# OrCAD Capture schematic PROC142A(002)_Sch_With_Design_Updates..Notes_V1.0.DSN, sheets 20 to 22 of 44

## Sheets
20 19. SD CARD INTERFACE: size C; title: SD CARD INTERFACE
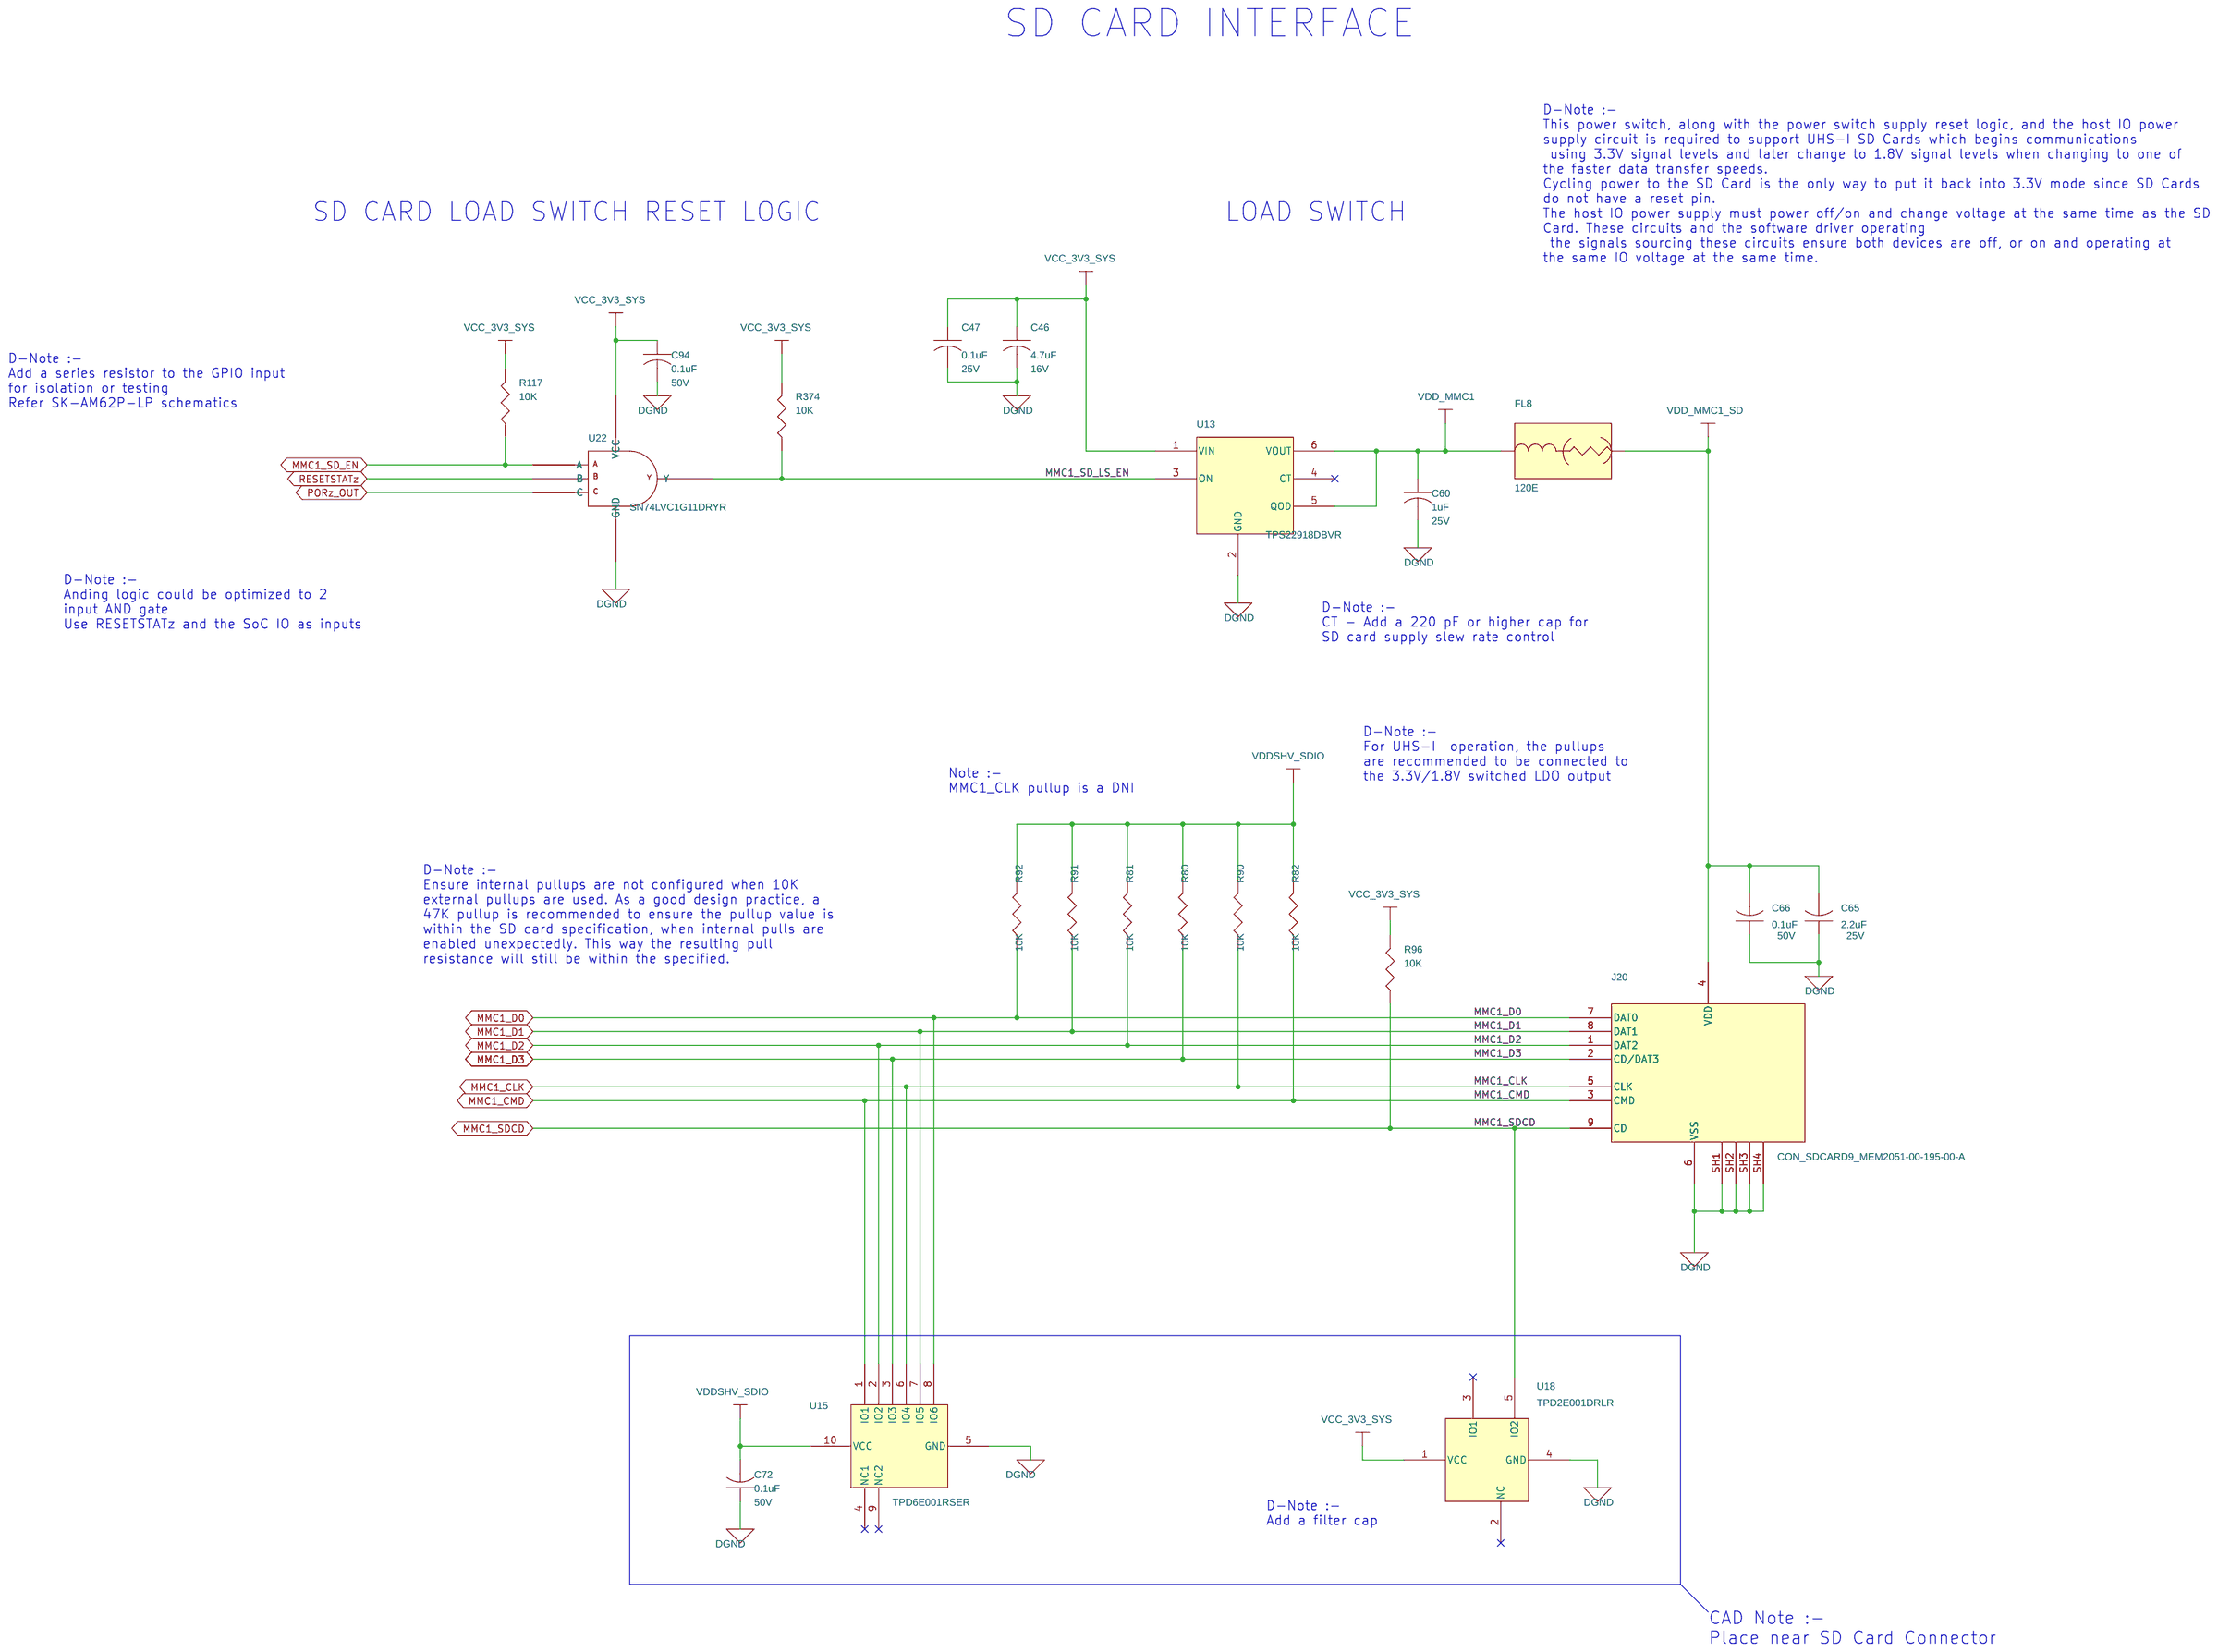
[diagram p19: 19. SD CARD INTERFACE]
21 20. OSPI INTERFACE: size C; title: OSPI INTERFACE
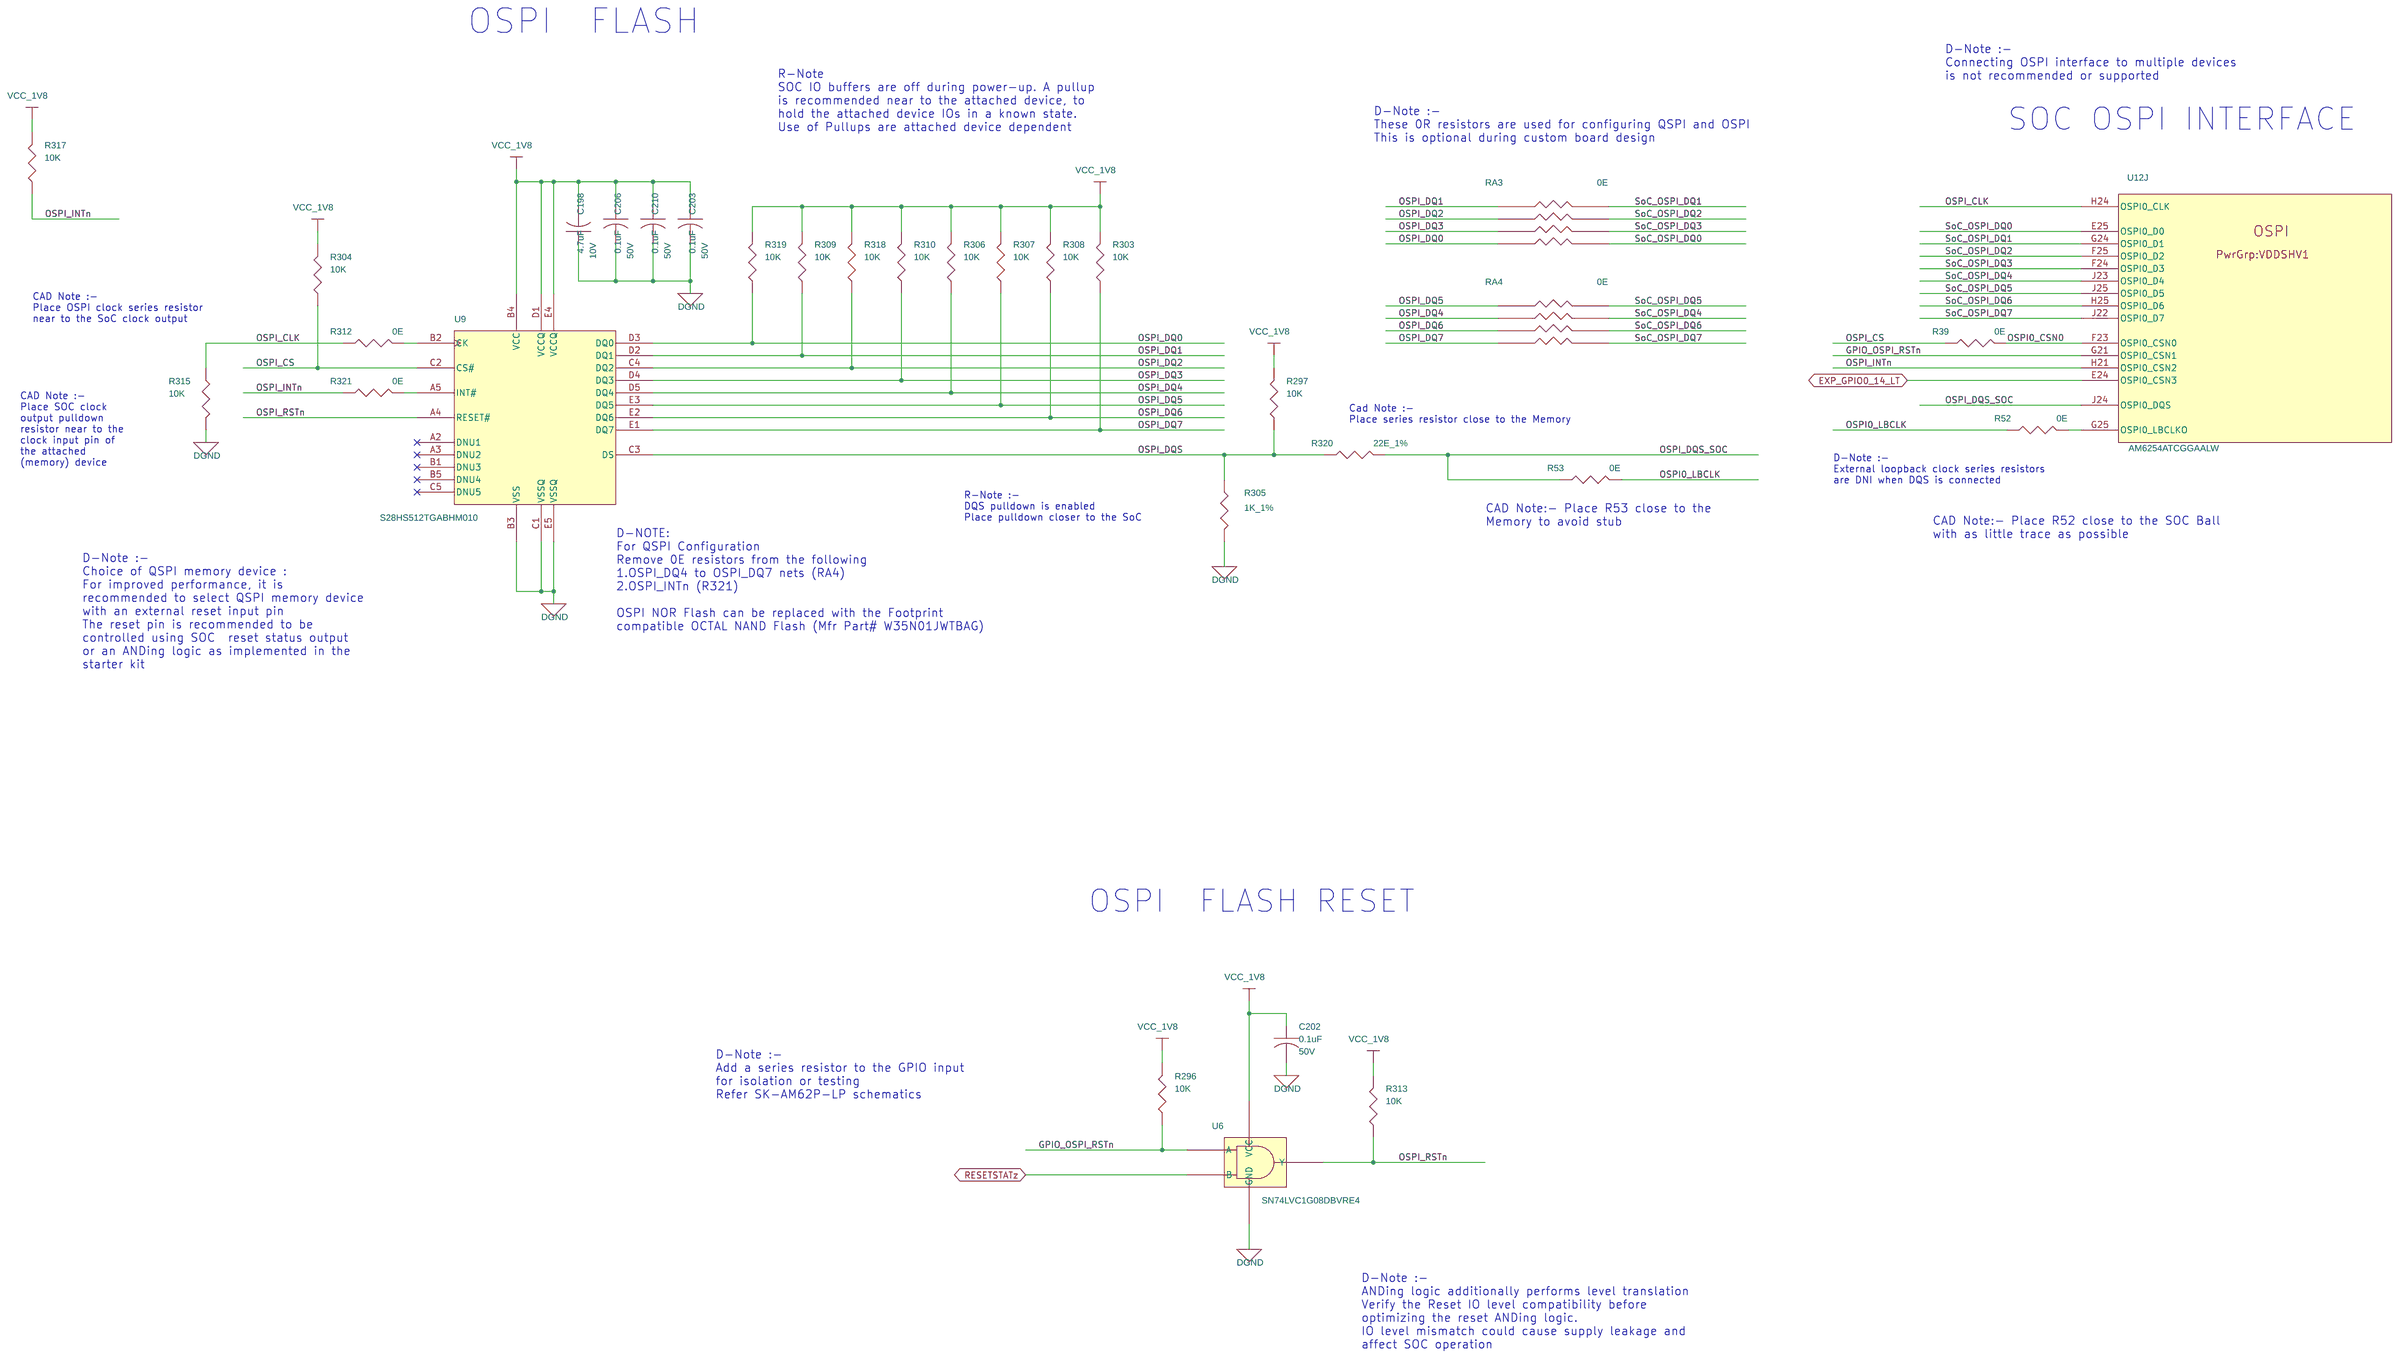
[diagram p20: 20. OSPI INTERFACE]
22 21. BRD ID EEPROM &TEMP SENSORS: size C; title: BOARD ID EEPROM & TEMPERATURE SENSORS
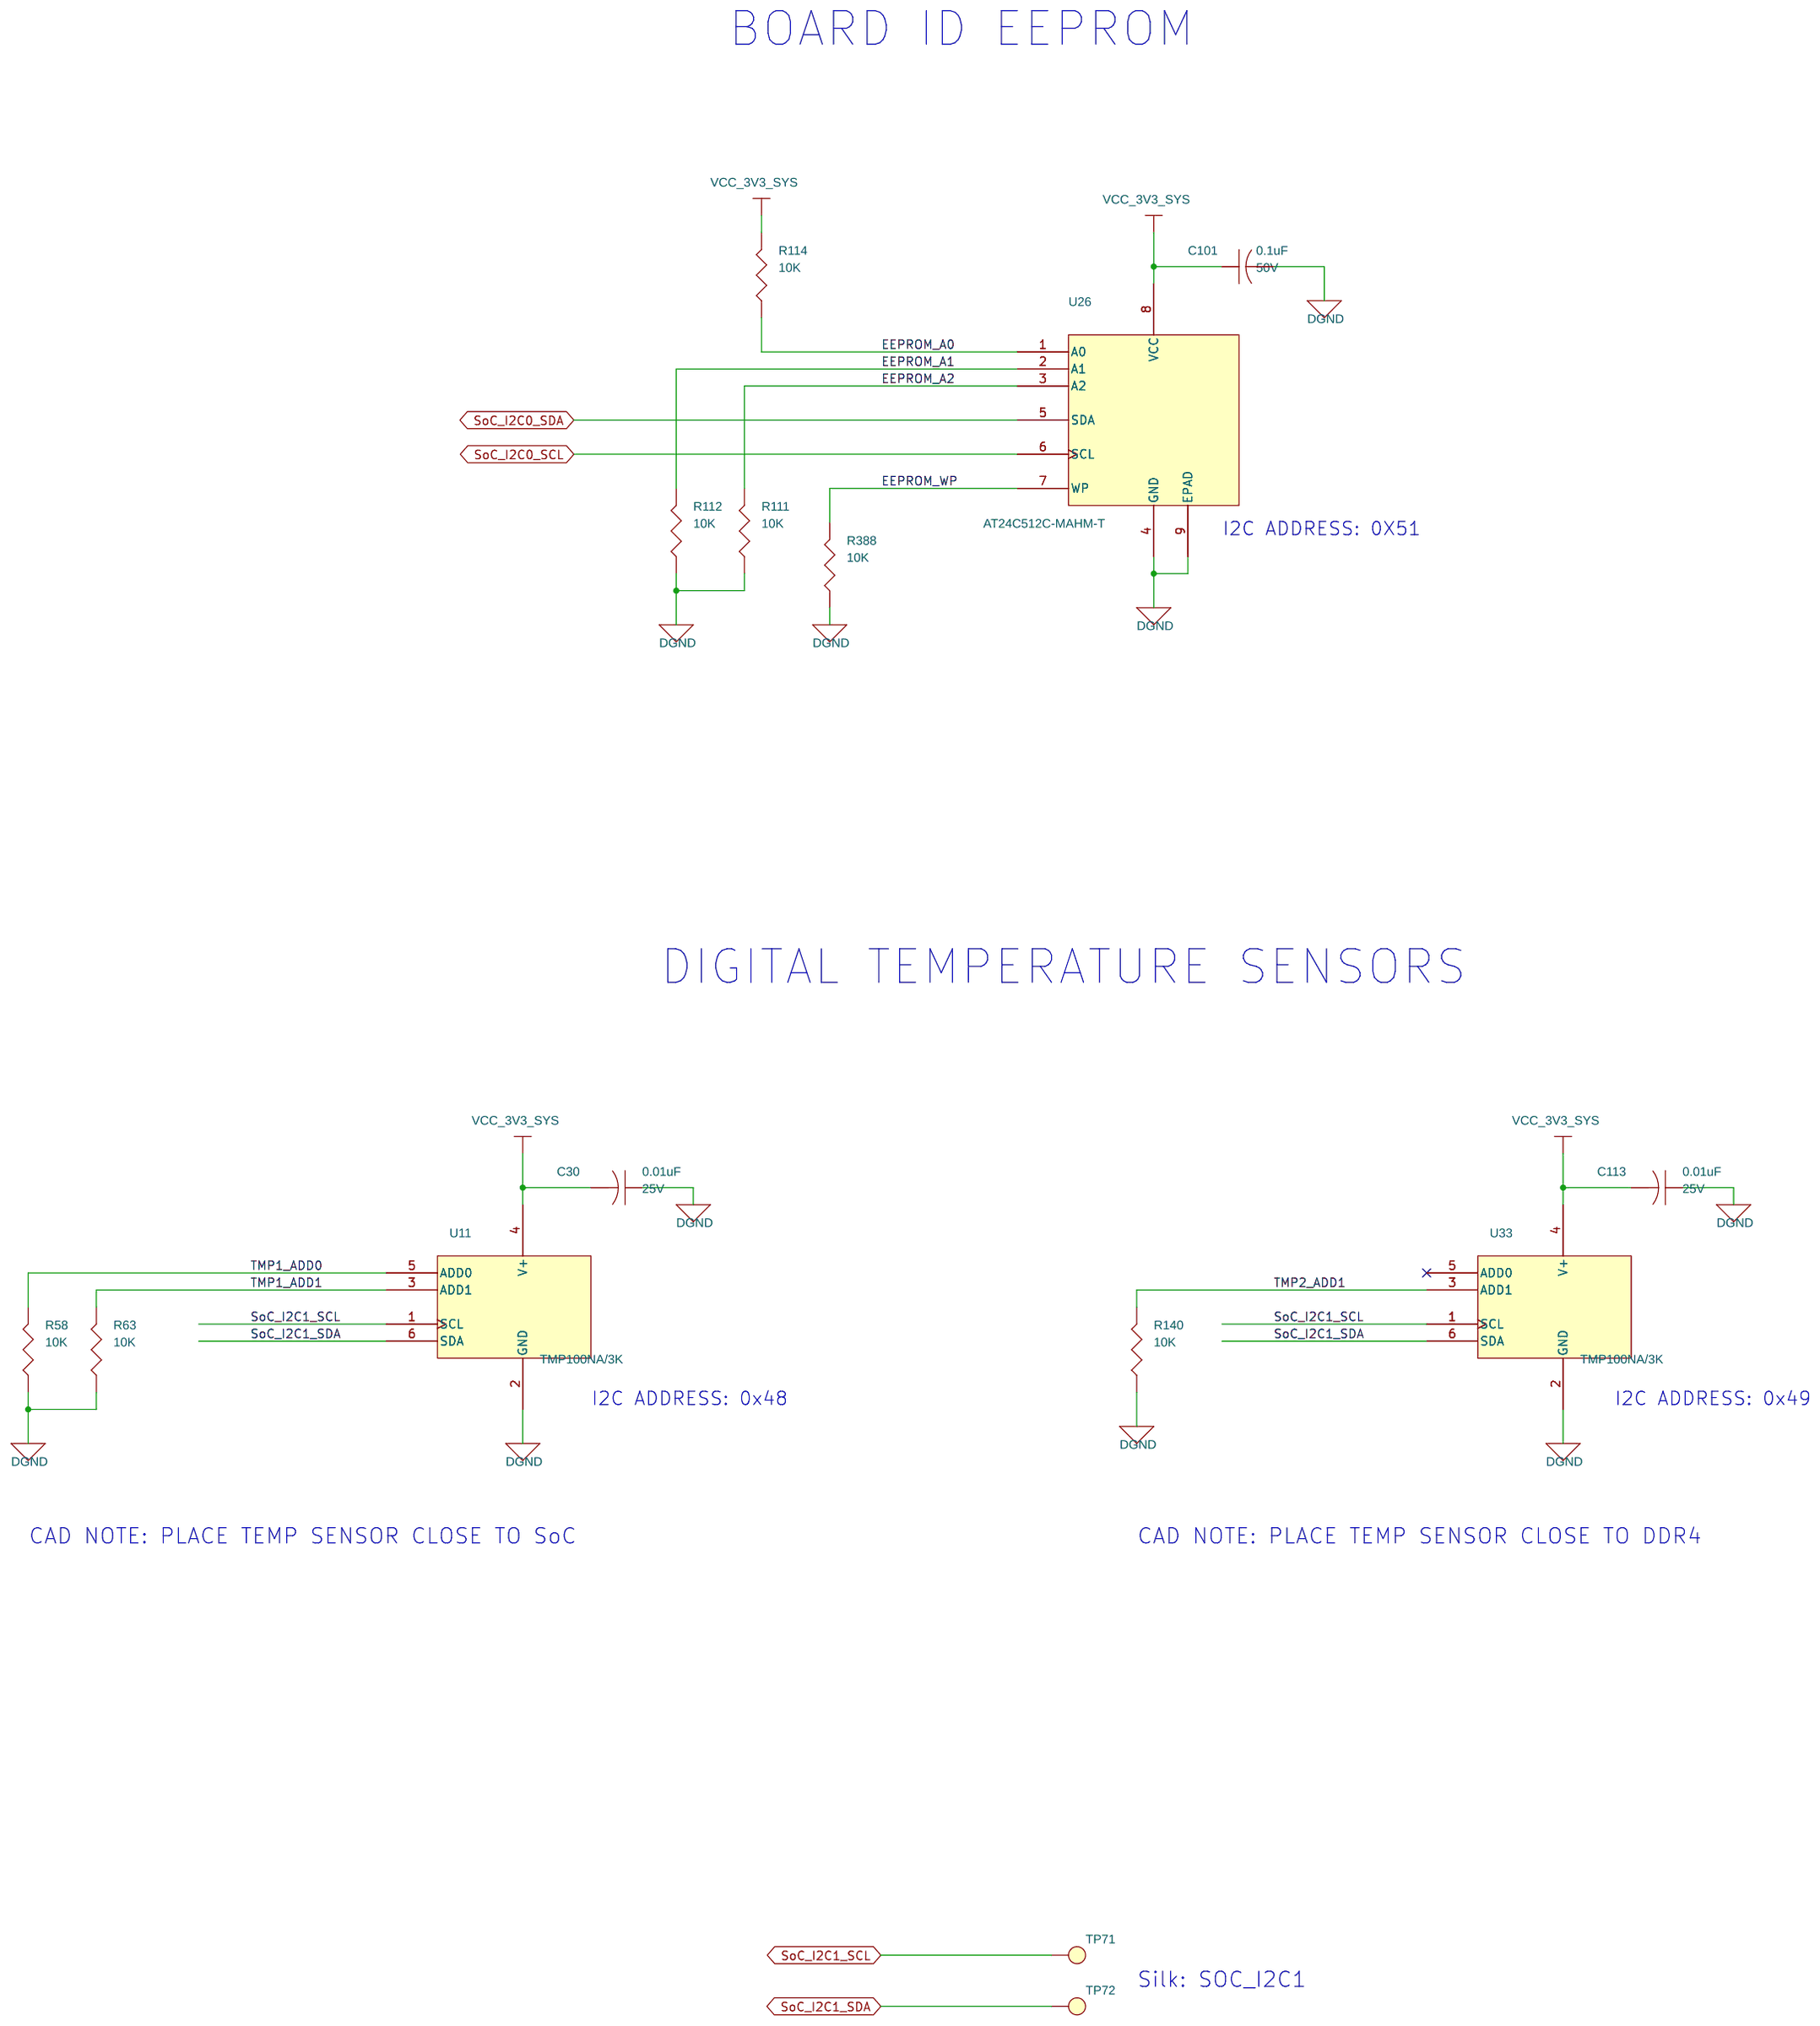
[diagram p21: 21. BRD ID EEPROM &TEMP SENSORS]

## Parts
sheet 19. SD CARD INTERFACE
C46  4.7uF  [CAP0402_0-75]
C47  0.1uF  [CAP0201_0-5]
C60  1uF  [CAP0402_0-75]
C65  2.2uF  [CAP0402_0-75]
C66  0.1uF  [CAP0402_0-75]
C72  0.1uF  [CAP0402_0-75]
C94  0.1uF  [CAP0402_0-75]
FL8  120E  [EMIFIL_BLM15A_0402_0-6]
J20  CON_SDCARD9_MEM2051-00-195-00-A  [CON_SD9_MEM2051-00-195-00_S_R_S_2-1]
R80  10K  [RES0201_0-5]
R81  10K  [RES0201_0-5]
R82  10K  [RES0201_0-5]
R90  10K  [RES0201_0-5]
R91  10K  [RES0201_0-5]
R92  10K  [RES0201_0-5]
R96  10K  [RES0201_0-5]
R117  10K  [RES0201_0-5]
R374  10K  [RES0201_0-5]
U13  TPS22918DBVR  [SOT23-6]
U15  TPD6E001RSER  [UQFN10_19-68_80X60_0-6]
U18  TPD2E001DRLR  [SOT553-5_0-6]
U22  SN74LVC1G11DRYR  [SON6_SN74LVC2G17_40X60_0-6]
sheet 20. OSPI INTERFACE
C198  4.7uF  [CAP0402_0-75]
C202  0.1uF  [CAP0402_0-75]
C203  0.1uF  [CAP0402_0-75]
C206  0.1uF  [CAP0402_0-75]
C210  0.1uF  [CAP0402_0-75]
R39  0E  [RES0201_0-5]
R52  0E  [RES0201_0-5]
R53  0E  [RES0201_0-5]
R296  10K  [RES0201_0-5]
R297  10K  [RES0201_0-5]
R303  10K  [RES0201_0-5]
R304  10K  [RES0201_0-5]
R305  1K_1%  [RES0402_0-5]
R306  10K  [RES0201_0-5]
R307  10K  [RES0201_0-5]
R308  10K  [RES0201_0-5]
R309  10K  [RES0201_0-5]
R310  10K  [RES0201_0-5]
R312  0E  [RES0402_0-5]
R313  10K  [RES0201_0-5]
R315  10K  [RES0201_0-5]
R317  10K  [RES0201_0-5]
R318  10K  [RES0201_0-5]
R319  10K  [RES0201_0-5]
R320  22E_1%  [RES0201_0-5]
R321  0E  [RES0402_0-5]
RA3  0E  [RESA_EXB_0201-4_0-5]
RA4  0E  [RESA_EXB_0201-4_0-5]
U6  SN74LVC1G08DBVRE4  [SOT23-5]
U9  S28HS512TGABHM010  [BGA24_39-37_240X310_1]
sheet 21. BRD ID EEPROM &TEMP SENSORS
C30  0.01uF  [CAP0201_0-5]
C101  0.1uF  [CAP0402_0-75]
C113  0.01uF  [CAP0201_0-5]
R58  10K  [RES0201_0-5]
R63  10K  [RES0201_0-5]
R111  10K  [RES0201_0-5]
R112  10K  [RES0201_0-5]
R114  10K  [RES0201_0-5]
R140  10K  [RES0201_0-5]
R388  10K  [RES0201_0-5]
TP71  THRU HOLE  [TP_36X22]
TP72  THRU HOLE  [TP_36X22]
U11  TMP100NA/3K  [SOT23-6_1-5]
U26  AT24C512C-MAHM-T  [UDFN8_19-68_120X80_0-6]
U33  TMP100NA/3K  [SOT23-6_1-5]
sheet 42. OSCILLATOR
U12  AM6254ATCGGAALW  [BGA425_19-68_510X510_0-7]  (sections A,B,C,D,E,F,G,H,I,J,K,L,M,N,O,P,Q,R)

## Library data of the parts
C46 = CAP: CAP CERAMIC 4.7uF 16V 20% X5R 0402; Alt_Mfr_name: YAGEO AMERICA; Alt_Mfr_part_number: CC0402KRX5R8BB104; Chkd/date: MANIRAJA/061218; Crtd /date: ALVY/061218; Custom_Duty: 15%; Customs_HS_Code: 85322990; Distributor_name: DIGIKEY; Distributor_part_number: 311-3482-1-ND; Footprint Path: Y:\MIS_DATABASE\Library\ALTIUM_TOOL\PCB_FOOTPRINTS\Altium_Footprint_Lib.PcbLib; Height: 0.65MM; Library Path: Y:\MIS_DATABASE\Library\ALTIUM_TOOL\SCHEMATICS_PARTS\MS_DISCRETE_Library.schlib; Mfr_name: YAGEO AMERICA; Mfr_part_number: CC0402MRX5R7BB475; Mistral Part No: 120017100010-R; Package: 0402; Part_type: CAPACITORS\CERAMIC; Project: RFSU_POC-CARD; RoHS: RoHS; Temperature: -55°C+85°C; Tolerance: 20%; Voltage: 16V; Wattage: NA; Weight: NA; Datasheet: Y:\MIS_DATABASE\DATASHEETS\CAPACITORS\YACC-X5R.PDF
C47 = CAP: CAP CERAMIC 0.1uF 25V 10% X5R 0201; Chkd/date: PRAVEEN/131222; Crtd /date: TAMILARASU/131222; Custom_Duty: 15%; Customs_HS_Code: 85322990; Distributor_name: DIGIKEY; Distributor_part_number: 490-12686-1-ND; Footprint Path: Y:\MIS_DATABASE\Library\ALTIUM_TOOL\PCB_FOOTPRINTS\Altium_Footprint_Lib.PcbLib; Height: 0.33MM; Library Path: Y:\MIS_DATABASE\Library\ALTIUM_TOOL\SCHEMATICS_PARTS\MS_DISCRETE_Library.schlib; Mfr_name: MURATA; Mfr_part_number: GRM033R61E104KE14D; Mistral Part No: 120022120017-R; Package: 0201; Part_type: CAPACITORS\CERAMIC; Project: CLOUD RADAR; RoHS: RoHS; Temperature: -55°C+85°C; Tolerance: 10%; Voltage: 25V; Wattage: NA; Weight: 0.33mg; Datasheet: Y:\MIS_DATABASE\DATASHEETS\CAPACITORS\GRM033R61E104KE14D.PDF
C60 = CAP: CAP CERAMIC 1uF 25V 10% X5R AUTO 0402; Chkd/date: MANIRAJA/290318; Crtd /date: ALVY/280318; Custom_Duty: 15%; Customs_HS_Code: 85322990; Distributor_name: DIGIKEY; Distributor_part_number: 490-12263-1-ND; Footprint Path: Y:\MIS_DATABASE\Library\ALTIUM_TOOL\PCB_FOOTPRINTS\Altium_Footprint_Lib.PcbLib; Height: 0.55MM; Library Path: Y:\MIS_DATABASE\Library\ALTIUM_TOOL\SCHEMATICS_PARTS\MS_DISCRETE_Library.schlib; Mfr_name: MURATA; Mfr_part_number: GRT155R61E105KE01D; Mistral Part No: 120019040035-R; Package: 0402; Part_type: CAPACITORS\CERAMIC; Project: NPOL_SAR_ADC; RoHS: RoHS; Temperature: -55°C+85°C; Tolerance: 10%; Voltage: 25V; Wattage: NA; Weight: 0.65mg; Datasheet: Y:\MIS_DATABASE\DATASHEETS\CAPACITORS\GRT155R61E105KE01D.PDF
C65 = CAP: CAP CERAMIC 2.2uF 25V 10% X5R 0402; Chkd/date: ALVY/010721; Crtd /date: MANIRAJA/010721; Custom_Duty: 15%; Customs_HS_Code: 85322990; Distributor_name: DIGIKEY; Distributor_part_number: 490-12703-1-ND; Footprint Path: Y:\MIS_DATABASE\Library\ALTIUM_TOOL\PCB_FOOTPRINTS\Altium_Footprint_Lib.PcbLib; Height: 0.70MM; Library Path: Y:\MIS_DATABASE\Library\ALTIUM_TOOL\SCHEMATICS_PARTS\MS_DISCRETE_Library.schlib; Mfr_name: MURATA; Mfr_part_number: GRM155R61E225KE11D; Mistral Part No: 120015120001-R; Package: 0402; Part_type: CAPACITORS\CERAMIC; Project: TI_AM263X_CC; RoHS: RoHS; Temperature: -55°C+85°C; Tolerance: 10%; Voltage: 25V; Wattage: NA; Weight: 1.5mg; Datasheet: Y:\MIS_DATABASE\DATASHEETS\CAPACITORS\GRM155R61E225KE11.PDF
C66 C72 C94 C101 C202 C203 C206 C210 = CAP: CAP CERAMIC 0.1uF 50V 10% X7R 0402; Alt_Mfr_name: YAGEO AMERICA; Alt_Mfr_part_number: CC0402KRX5R8BB104; Chkd/date: MANIRAJA/261020; Crtd /date: ALVY/211020; Custom_Duty: 15%; Customs_HS_Code: 85322990; Distributor_name: DIGIKEY; Distributor_part_number: 490-10700-1-ND; Footprint Path: Y:\MIS_DATABASE\Library\ALTIUM_TOOL\PCB_FOOTPRINTS\Altium_Footprint_Lib.PcbLib; Height: 0.55MM; Library Path: Y:\MIS_DATABASE\Library\ALTIUM_TOOL\SCHEMATICS_PARTS\MS_DISCRETE_Library.schlib; Mfr_name: MURATA; Mfr_part_number: GRM155R71H104KE14D; Mistral Part No: 120011100014-R; Package: 0402; Part_type: CAPACITORS\CERAMIC; Project: J7_CP; RoHS: RoHS; Temperature: -55°C+125°C; Tolerance: 10%; Voltage: 50V; Wattage: NA; Weight: 3.1mg; Datasheet: Y:\MIS_DATABASE\DATASHEETS\CAPACITORS\GRM155R71H104KE14.PDF
FL8 = EMIFILTER_IND: IND FERRITE BEAD CHIP 120E 2A 0402; Chkd/date: NAVEED/241114; Crtd /date: USMAN/170613; Custom_Duty: 24%; Customs_HS_Code: 85369090; Distributor_name: DIGIKEY; Distributor_part_number: 490-9656-1-ND; Footprint Path: Y:\MIS_DATABASE\Library\ALTIUM_TOOL\PCB_FOOTPRINTS\Altium_Footprint_Lib.PcbLib; Height: 0.55MM; Library Path: Y:\MIS_DATABASE\Library\ALTIUM_TOOL\SCHEMATICS_PARTS\MS_FILTER_Library.schlib; Mfr_name: MURATA; Mfr_part_number: BLM15PX121SN1D; Mistral Part No: 130013060022-R; Package: 0402; Part_type: INDUCTOR; Project: GEN_3-8; RoHS: RoHS; Temperature: -55°C+125°C; Tolerance: 25%; Voltage: NA; Wattage: NA; Weight: 1mg; Datasheet: Y:\MIS_DATABASE\DATASHEETS\DISCRETES\INDUCTORS\BLM15-SN1-SER.PDF
J20 = CON_SDCARD9_MEM2075-00-140: CON MICROSD CARD 9POS FEMALE RT SMD; Chkd/date: MANIRAJA/270921; Crtd /date: ALVY/240921; Custom_Duty: 24%; Customs_HS_Code: 85369090; Distributor_name: DIGIKEY; Distributor_part_number: 2073-MEM2051-00-195-00-ACT-ND; Footprint Path: Y:\MIS_DATABASE\Library\ALTIUM_TOOL\PCB_FOOTPRINTS\Altium_Footprint_Lib.PcbLib; Height: 2.05MM; Library Path: Y:\MIS_DATABASE\Library\ALTIUM_TOOL\SCHEMATICS_PARTS\MS_CONNECTOR_Library.schlib; Mfr_name: GCT; Mfr_part_number: MEM2051-00-195-00-A; Mistral Part No: 150021090028-R; Package: SMD; Part_type: CONNECTOR\MEMORY CARD; Project: TI_AM62x SKEVM_BRD; RoHS: RoHS; Temperature: -40°C+85°C; Tolerance: NA; Voltage: NA; Wattage: NA; Weight: 1000mg; Datasheet: Y:\MIS_DATABASE\DATASHEETS\CONNECTORS\MEM2051-00-195-00-A.PDF
R58 R63 R80-R82 R90-R92 R96 R111 R112 R114 R117 R140 R296 R297 R303 R304 R306-R310 R313 R315 R317-R319 R374 R388 = RESISTOR: RES 10K 1/20W 5% 0201; Chkd/date: MANIRAJA/050517; Crtd /date: MANIRAJA/050517; Custom_Duty: 15%; Customs_HS_Code: 85332119; Distributor_name: DIGIKEY; Distributor_part_number: 311-10KNCT-ND; Footprint Path: Y:\MIS_DATABASE\Library\ALTIUM_TOOL\PCB_FOOTPRINTS\Altium_Footprint_Lib.PcbLib; Height: 0.26MM; Library Path: Y:\MIS_DATABASE\Library\ALTIUM_TOOL\SCHEMATICS_PARTS\MS_DISCRETE_Library.schlib; Mfr_name: YAGEO AMERICA; Mfr_part_number: RC0201JR-0710KL; Mistral Part No: 110010070051-R; Package: 0201; Part_type: RESISTORS\FIXED; Project: GOLDEN-I LITE; RoHS: RoHS; Temperature: -55°C+125°C; Tolerance: 5%; Voltage: NA; Wattage: 1/20W; Weight: 0.17mg; Datasheet: Y:\MIS_DATABASE\DATASHEETS\RESISTORS\RCXXXXL-SER_MAR18.PDF
U13 = TPS22918DBVR_SOT23-6: IC ON RESISTANCE LOAD SWITCH SOT23-6; Automotive Alternate_mfr_name: TEXAS INSTRUMENTS; Automotive Alternate_mfr_part_number: TPS22918TDBVRQ1; Chkd/date: VASANTHA/130516; Crtd /date: VASANTHA/130516; Custom_Duty: 15%; Customs_HS_Code: 85423100; Distributor_name: DIGIKEY; Distributor_part_number: TPS22918DBVR-ND; Height: 1.45MM; Mfr_name: TEXAS INSTRUMENTS; Mistral Part No: 142016050007-R; Part_type: ICS\POWER; Project: TMDXCSK8127; RoHS: RoHS; Temperature: -40°C to 105°C; Tolerance: NA; Voltage: NA; Wattage: NA; Weight: NA; Datasheet: Y:\MIS_DATABASE\DATASHEETS\ICS\POWER\TPS22918DBV.PDF
U15 = TPD6E001RSE_UQFN10: IC 6CH ESD-PROTECTION ARRAY UQFN10; Chkd/date: USMAN/070612; Crtd /date: BAVISH/160811; Custom_Duty: 15%; Customs_HS_Code: 85423100; Distributor_name: DIGIKEY; Distributor_part_number: 296-21888-1-ND; Footprint Path: Y:\MIS_DATABASE\Library\ALTIUM_TOOL\PCB_FOOTPRINTS\Altium_Footprint_Lib.PcbLib; Height: 0.60MM; IBISSP_MODLES: Y:\MIS_DATABASE\IBIS\ICs\INTERFACE\TPD6E001RSE.IBS; Library Path: Y:\MIS_DATABASE\Library\ALTIUM_TOOL\SCHEMATICS_PARTS\MS_MISCINTERFACE_Library.schlib; Mfr_name: TEXAS INSTRUMENTS; Mistral Part No: 141011080020-R; Package: UQFN10; Part_type: ICS\INTERFACE; Project: DM385EVM_BASE-BOARD; RoHS: RoHS; Temperature: -40°C+85°C; Tolerance: NA; Voltage: NA; Wattage: NA; Weight: 7mg; Datasheet: Y:\MIS_DATABASE\DATASHEETS\ICS\INTERFACE\TPD6E001.PDF
U18 = TPD2E001DRLR_SOT-5: IC ESD-PROTECTION DIODE ARRAYS SOT-5; Chkd/date: NAVEED/150714; Crtd /date: MUDDU/250510; Custom_Duty: 15%; Customs_HS_Code: 85423100; Distributor_name: DIGIKEY; Distributor_part_number: 296-21883-1-ND; Footprint Path: Y:\MIS_DATABASE\Library\ALTIUM_TOOL\PCB_FOOTPRINTS\Altium_Footprint_Lib.PcbLib; Height: 0.60MM; Library Path: Y:\MIS_DATABASE\Library\ALTIUM_TOOL\SCHEMATICS_PARTS\MS_FILTER_Library.schlib; Mfr_name: TEXAS INSTRUMENTS; Mistral Part No: 140110060007-R; Package: SOT-5; Part_type: ICS\ANALOG\ACTIVE FILTER; Project: CENTAURUS; RoHS: RoHS; Temperature: -40°C+85°C; Tolerance: NA; Voltage: NA; Wattage: NA; Weight: 2.8mg; Datasheet: Y:\MIS_DATABASE\DATASHEETS\ICS\MISC\TPD2E001DRLR.PDF
U22 = SN74LVC1G11DCKR_SC70-6: IC SINGLE 3-INPUT POSITIVE-AND GATE SON6; Chkd/date: MANIRAJA/270121; Crtd /date: ALVY/270121; Custom_Duty: 15%; Customs_HS_Code: 85423100; Distributor_name: DIGIKEY; Distributor_part_number: 296-30120-1-ND; Footprint Path: Y:\MIS_DATABASE\Library\ALTIUM_TOOL\PCB_FOOTPRINTS\Altium_Footprint_Lib.PcbLib; Height: 0.60MM; Library Path: Y:\MIS_DATABASE\Library\ALTIUM_TOOL\SCHEMATICS_PARTS\MS_GATE_Library.schlib; Mfr_name: TEXAS INSTRUMENTS; Mistral Part No: 141021010013-R; Package: SON6; Part_type: ICS\DIGITAL\GATES; Project: AM64X_SKEVM; RoHS: RoHS; Temperature: -40°C+125°C; Tolerance: NA; Voltage: NA; Wattage: NA; Weight: 33mg; Datasheet: Y:\MIS_DATABASE\DATASHEETS\ICS\DIGITAL\GATES\SN74LVC1G_NOV16.PDF
C198 = CAP: CAP CERAMIC 4.7uF 10V 20% X5R 0402; Chkd/date: MANIRAJA/110718; Crtd /date: ALVY/110718; Custom_Duty: 15%; Customs_HS_Code: 85322990; Distributor_name: DIGIKEY; Distributor_part_number: 490-14306-1-ND; Footprint Path: Y:\MIS_DATABASE\Library\ALTIUM_TOOL\PCB_FOOTPRINTS\Altium_Footprint_Lib.PcbLib; Height: 0.65MM; Library Path: Y:\MIS_DATABASE\Library\ALTIUM_TOOL\SCHEMATICS_PARTS\MS_DISCRETE_Library.schlib; Mfr_name: MURATA; Mfr_part_number: GRM155R61A475MEAAD; Mistral Part No: 120012060002-R; Package: 0402; Part_type: CAPACITORS\CERAMIC; Project: TI_J7SVB_PCIE_ADD-ON-CARD; RoHS: RoHS; Temperature: -55°C+85°C; Tolerance: 20%; Voltage: 10V; Wattage: NA; Weight: 14mg; Datasheet: Y:\MIS_DATABASE\DATASHEETS\CAPACITORS\GRM155R61A475MEAAD.PDF
R39 R52 R53 = RESISTOR: RES 0E 1/20W 5% 0201; Chkd/date: NAVEED/301214; Crtd /date: MUDDU/120710; Custom_Duty: 15%; Customs_HS_Code: 85332119; Distributor_name: DIGIKEY; Distributor_part_number: 311-0.0NCT-ND; Footprint Path: Y:\MIS_DATABASE\Library\ALTIUM_TOOL\PCB_FOOTPRINTS\Altium_Footprint_Lib.PcbLib; Height: 0.26MM; Library Path: Y:\MIS_DATABASE\Library\ALTIUM_TOOL\SCHEMATICS_PARTS\MS_DISCRETE_Library.schlib; Mfr_name: YAGEO AMERICA; Mfr_part_number: RC0201JR-070RL; Mistral Part No: 110010070067-R; Package: 0201; Part_type: RESISTORS\FIXED; Project: PB_BUGBASE; RoHS: RoHS; SIGNAL_MODEL: RESISTOR_RES0201_0-5_0E_0E; Temperature: -55°C+125°C; Tolerance: 5%; Voltage: NA; Wattage: 1/20W; Weight: 0.17mg; Datasheet: Y:\MIS_DATABASE\DATASHEETS\RESISTORS\RCXXXXL-SER_MAR18.PDF
R305 = RESISTOR: RES 1K 1/10W 1% 0402; Chkd/date: VASANTHA/281216; Crtd /date: MAZHAR/150506; Custom_Duty: 15%; Customs_HS_Code: 85332119; Distributor_name: DIGIKEY; Distributor_part_number: P1.00KLCT-ND; Footprint Path: Y:\MIS_DATABASE\Library\ALTIUM_TOOL\PCB_FOOTPRINTS\Altium_Footprint_Lib.PcbLib; Height: 0.40MM; Library Path: Y:\MIS_DATABASE\Library\ALTIUM_TOOL\SCHEMATICS_PARTS\MS_DISCRETE_Library.schlib; Mfr_name: PANASONIC-ECG; Mfr_part_number: ERJ-2RKF1001X; Mistral Part No: 110009030411-R; Package: 0402; Part_type: RESISTORS\FIXED; Project: VOCERA; RoHS: RoHS; Temperature: -55°C+155°C; Tolerance: 1%; Voltage: NA; Wattage: 1/10W; Weight: 0.8mg; Datasheet: Y:\MIS_DATABASE\DATASHEETS\RESISTORS\PAN-ERJSER_NOV17.PDF
R312 = RESISTOR: RES 0E 1/16W JUMPER 0402; Chkd/date: VASANTHA/201216; Crtd /date: MUDDU/190810; Custom_Duty: 15%; Customs_HS_Code: 85332119; Distributor_name: DIGIKEY; Distributor_part_number: 541-0.0JCT-ND; Footprint Path: Y:\MIS_DATABASE\Library\ALTIUM_TOOL\PCB_FOOTPRINTS\Altium_Footprint_Lib.PcbLib; Height: 0.40MM; Library Path: Y:\MIS_DATABASE\Library\ALTIUM_TOOL\SCHEMATICS_PARTS\MS_DISCRETE_Library.schlib; Mfr_name: VISHAY; Mfr_part_number: CRCW04020000Z0ED; Mistral Part No: 110010080019-R; Package: 0402; Part_type: RESISTORS\FIXED; Project: PB_BUGBASE; RoHS: RoHS; SIGNAL_MODEL: RESISTOR_RES0402_0-5_0E_0E; Temperature: -55°C+155°C; Tolerance: NA; Voltage: NA; Wattage: 1/16W; Weight: 0.65mg; Datasheet: Y:\MIS_DATABASE\DATASHEETS\RESISTORS\CRCW0603.PDF
R320 = RESISTOR: RES 22E 1/20W 1% 0201; Chkd/date: MAZHAR/140709; Crtd /date: MAZHAR/220807; Custom_Duty: 15%; Customs_HS_Code: 85332119; Distributor_name: DIGIKEY; Distributor_part_number: P22.0ABCT-ND; Footprint Path: Y:\MIS_DATABASE\Library\ALTIUM_TOOL\PCB_FOOTPRINTS\Altium_Footprint_Lib.PcbLib; Height: 0.26MM; Library Path: Y:\MIS_DATABASE\Library\ALTIUM_TOOL\SCHEMATICS_PARTS\MS_DISCRETE_Library.schlib; Mfr_name: PANASONIC-ECG; Mfr_part_number: ERJ-1GEF22R0C; Mistral Part No: 110009030522-R; Package: 0201; Part_type: RESISTORS\FIXED; Project: V8TS; RoHS: RoHS; SIGNAL_MODEL: RESISTOR_RES0201_0-5_22E_1%_22E_1%; Temperature: -55°C+125°C; Tolerance: 1%; Voltage: NA; Wattage: 1/20W; Weight: 0.15mg; Datasheet: Y:\MIS_DATABASE\DATASHEETS\RESISTORS\PAN-ERJSER_NOV17.PDF
R321 = RESISTOR: RES 0E 1/16W JUMPER 0402; Chkd/date: VASANTHA/201216; Crtd /date: MUDDU/190810; Custom_Duty: 15%; Customs_HS_Code: 85332119; Distributor_name: DIGIKEY; Distributor_part_number: 541-0.0JCT-ND; Footprint Path: Y:\MIS_DATABASE\Library\ALTIUM_TOOL\PCB_FOOTPRINTS\Altium_Footprint_Lib.PcbLib; Height: 0.40MM; Library Path: Y:\MIS_DATABASE\Library\ALTIUM_TOOL\SCHEMATICS_PARTS\MS_DISCRETE_Library.schlib; Mfr_name: VISHAY; Mfr_part_number: CRCW04020000Z0ED; Mistral Part No: 110010080019-R; Package: 0402; Part_type: RESISTORS\FIXED; Project: PB_BUGBASE; RoHS: RoHS; Temperature: -55°C+155°C; Tolerance: NA; Voltage: NA; Wattage: 1/16W; Weight: 0.65mg; Datasheet: Y:\MIS_DATABASE\DATASHEETS\RESISTORS\CRCW0603.PDF
RA3 RA4 = RESARR_ISO4: RES ARRAY 0E 31mW JUMPER 0201-4; Chkd/date: MANIRAJA/290918; Crtd /date: MANIRAJA/290918; Custom_Duty: 15%; Customs_HS_Code: 85332119; Distributor_name: DIGIKEY; Distributor_part_number: Y6000CT-ND; Footprint Path: Y:\MIS_DATABASE\Library\ALTIUM_TOOL\PCB_FOOTPRINTS\Altium_Footprint_Lib.PcbLib; Height: 0.45MM; Library Path: Y:\MIS_DATABASE\Library\ALTIUM_TOOL\SCHEMATICS_PARTS\MS_DISCRETE_Library.schlib; Manufacturer: PANASONIC-ECG; Mfr_part_number: EXB-18VR000X; Mistral Part No: 110018090033-R; Package: 0201-4; Part_type: RESISTORS\ARRAY; Project: TI_60GHz-AOP; RoHS: RoHS; Temperature: -55°C+125°C; Tolerance: NA; Voltage: NA; Wattage: 31mW; Weight: 1mg; Datasheet: Y:\MIS_DATABASE\DATASHEETS\RESISTORS\EXB-18V.PDF
U6 = SN74LVC1G08DBVRE4_SOT23-5: IC SINGLE 2-INPUT POSITIVE AND GATE SOT23-5; Chkd/date: SUHAS/221010; Crtd /date: USMAN/151008; Custom_Duty: 15%; Customs_HS_Code: 85423100; Distributor_name: DIGIKEY; Distributor_part_number: SN74LVC1G08DBVRE4-ND; Height: 1.45MM; Mfr_name: TEXAS INSTRUMENTS; Mistral Part No: 141009060026-R; Part_type: ICS\DIGITAL\GATES; Project: KHAN_MAIN; RoHS: Sb/ Br FREE; Temperature: -40°C+85°C; Datasheet: Y:\MIS_DATABASE\DATASHEETS\ICS\DIGITAL\GATES\SN74LVC1G08.PDF
U9 = S28HS512T_BGA24: IC 1.8V 512Mb SEMPER FLASH WITH OCTAL INTERFACE BGA24; Chkd/date: MANIRAJA/170120; Crtd /date: ALVY/170120; Custom_Duty: 15%; Customs_HS_Code: 85423100; Distributor_name: NA; Distributor_part_number: NA; Footprint Path: Y:\MIS_DATABASE\Library\ALTIUM_TOOL\PCB_FOOTPRINTS\Altium_Footprint_Lib.PcbLib; Height: 1.00MM; Library Path: Y:\MIS_DATABASE\Library\ALTIUM_TOOL\SCHEMATICS_PARTS\MS_MISCMEMORY_Library.schlib; Mfr_name: CYPRESS SEMICONDUCTOR; Mistral Part No: 141120010002; Package: BGA24; Part_type: ICS\DIGITAL\MEMORY; Project: J7VCL_SOM DUAL LEO PMIC; RoHS: NA; Temperature: -40°C+125°C; Tolerance: NA; Voltage: NA; Wattage: NA; Weight: NA; Datasheet: Y:\MIS_DATABASE\DATASHEETS\ICS\MEMORY\S28HS512T.PDF
C30 C113 = CAP: CAP CERAMIC 0.01uF 25V 10% X5R 0201; Chkd/date: MANIRAJA/230118; Crtd /date: MANIRAJA/230118; Custom_Duty: 15%; Customs_HS_Code: 85322990; Distributor_name: DIGIKEY; Distributor_part_number: GRM033R61E103KA12J-ND; Footprint Path: Y:\MIS_DATABASE\Library\ALTIUM_TOOL\PCB_FOOTPRINTS\Altium_Footprint_Lib.PcbLib; Height: 0.33MM; Library Path: Y:\MIS_DATABASE\Library\ALTIUM_TOOL\SCHEMATICS_PARTS\MS_DISCRETE_Library.schlib; Mfr_name: MURATA; Mfr_part_number: GRM033R61E103KA12J; Mistral Part No: 120018010007-R; Package: 0201; Part_type: CAPACITORS\CERAMIC; Project: TI_MAXIE_CPB; RoHS: RoHS; Temperature: -55°C+85°C; Tolerance: 10%; Voltage: 25V; Wattage: NA; Weight: 0.33mg; Datasheet: Y:\MIS_DATABASE\DATASHEETS\CAPACITORS\GRM033R61E103KA12.PDF
TP71 TP72 = TESTPOINT: TESTPOINT 0.56MM DRILL PTH; Chkd/date: BAVISH/040311; Crtd /date: MAZHAR/110405; Distributor_name: NA; Distributor_part_number: NA; Height: NA; Mfr_name: LOCAL; Mistral Part No: 130010010008; Package: THRU-HOLE; Project: KOPIN_MODULS; Temperature: NA; Tolerance: NA; Voltage: NA; Wattage: NA; Weight: NA; Datasheet: NA
U11 U33 = TMP100NA_3K_SOT23-6: IC TEMPERATURE SENSOR WITH I2C AND SMBUS INTERFACE SOT23-6; Chkd/date: MANIRAJA/290817; Crtd /date: MANIRAJA/290817; Custom_Duty: 15%; Customs_HS_Code: 85423100; Distributor_name: DIGIKEY; Distributor_part_number: 296-26833-1-ND; Height: 1.45MM; Library Ref: TMP100NA/3K_SOT23-6; Mfr_name: TEXAS INSTRUMENTS; Mistral Part No: 141017080030-R; Package: SOT23-6; Part_type: ICS\DIGITAL\PERIPHERAL; Project: TI_MAXIE_CPB; RoHS: RoHS; Temperature: -55°C+125°C; Tolerance: NA; Voltage: NA; Wattage: NA; Weight: 120mg; Datasheet: Y:\MIS_DATABASE\DATASHEETS\ICS\DIGITAL\PERIPHERAL\TMP10XX.PDF
U26 = AT24C64D-MAHM-T_UDFN8: IC 1.7-3.6V 512Kb I2C COMPATIBLE SERIAL EEPROM UDFN8; Chkd/date: MANIRAJA/240919; Crtd /date: ALVY/240919; Custom_Duty: 15%; Customs_HS_Code: 85423100; Distributor_name: DIGIKEY; Distributor_part_number: AT24C512C-MAHM-TCT-ND; Footprint Path: Y:\MIS_DATABASE\Library\ALTIUM_TOOL\PCB_FOOTPRINTS\Altium_Footprint_Lib.PcbLib; Height: 0.60MM; Library Path: Y:\MIS_DATABASE\Library\ALTIUM_TOOL\SCHEMATICS_PARTS\MS_MISCMEMORY_Library.schlib; Mfr_name: MICROCHIP; Mistral Part No: 141119090004-R; Package: UDFN8; Part_type: ICS\DIGITAL\MEMORY; Project: HAL_3U-T1042-SBC; RoHS: RoHS; Temperature: -40°C+85°C; Tolerance: NA; Voltage: NA; Wattage: NA; Weight: 9.5mg; Datasheet: Y:\MIS_DATABASE\DATASHEETS\ICS\MEMORY\AT24C512C.PDF
U12 = AM62-EVM_BGA425: IC AM62 SoC MICROPROCESSOR BGA425; Chkd/date: ALVY/110621; Crtd /date: MANIRAJA/110621; Custom_Duty: 15%; Customs_HS_Code: 85423100; Distributor_name: NA; Distributor_part_number: NA; Footprint Path: Y:\MIS_DATABASE\Library\ALTIUM_TOOL\PCB_FOOTPRINTS\Altium_Footprint_Lib.PcbLib; Height: 0.65MM; Library Path: Y:\MIS_DATABASE\Library\ALTIUM_TOOL\SCHEMATICS_PARTS\MS_MICROPROCESSOR_Library.schlib; Mfr_name: TEXAS INSTRUMENTS; Mistral Part No: 141221060001; Package: BGA425; Part_type: ICS\DIGITAL\MICROPROCESSOR; Project: AM62_EVM_BRD; RoHS: NA; Temperature: NA; Tolerance: NA; Voltage: NA; Wattage: NA; Weight: NA; Datasheet: Y:\MIS_DATABASE\DATASHEETS\ICS\DIGITAL\MICROCONTROLLER\AM62-SoC_SVB.PDF

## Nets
DGND: C30.1 C46.2 C47.2 C60.2 C65.1 C66.1 C72.1 C94.2 C101.2 C113.1 C198.1 C202.2 C203.2 C206.2 C210.2 J20.6(VSS) J20.SH1 J20.SH2 J20.SH3 J20.SH4 R58.2 R63.2 R111.2 R112.2 R140.2 R305.2 R315.2 R388.2 U6.3(GND) U9.B3(VSS) U9.C1(VSSQ) U9.E5(VSSQ) U11.2(GND) U13.2(GND) U15.5(GND) U18.4(GND) U22.2(GND) U26.4(GND) U26.9(EPAD) U33.2(GND) ; also on sheet 1 10 11 12 13 14 15 16 17 18 19 23 24 25 26 27 28 29 30 31 32 33 34 35 36 37 38 39 40 41 42 43
VCC_1V8: C198.2 C202.1 C203.1 C206.1 C210.1 R296.2 R297.2 R303.2 R304.2 R306.2 R307.2 R308.2 R309.2 R310.2 R313.2 R317.2 R318.2 R319.2 U6.5(VCC) U9.B4(VCC) U9.D1(VCCQ) U9.E4(VCCQ) ; also on sheet 12 13 14 18 19 25 34 37 39 40 42
VCC_3V3_SYS: C30.2 C46.1 C47.1 C94.1 C101.1 C113.2 R96.2 R114.1 R117.2 R374.2 U11.4(V+) U13.1(VIN) U18.1(VCC) U22.5(VCC) U26.8(VCC) U33.4(V+) ; also on sheet 10 12 13 14 18 19 23 24 25 26 27 29 30 31 32 33 34 35 36 37 38 39 40 41 42 43
VDD_MMC1: C60.1 FL8.1 U13.5(QOD) U13.6(VOUT)
VDD_MMC1_SD: C65.2 C66.2 FL8.2 J20.4(VDD)
VDDSHV_SDIO: C72.2 R80.2 R81.2 R82.2 R90.2 R91.2 R92.2 U15.10(VCC) ; also on sheet 13 15
EEPROM_A0: R114.2 U26.1(A0)
EEPROM_A1: R112.1 U26.2(A1)
EEPROM_A2: R111.1 U26.3(A2)
EEPROM_WP: R388.1 U26.7(WP)
EXP_GPIO0_14_LT: U12.E24(OSPI0_CSN3) ; also on sheet 34
GPIO_OSPI_RSTn: R296.1 U6.1(A) U12.G21(OSPI0_CSN1)
MMC1_CLK: J20.5(CLK) R90.1 U15.6(IO4) ; also on sheet 19
MMC1_CMD: J20.3(CMD) R82.1 U15.1(IO1) ; also on sheet 19
MMC1_D0: J20.7(DAT0) R92.1 U15.8(IO6) ; also on sheet 19
MMC1_D1: J20.8(DAT1) R91.1 U15.7(IO5) ; also on sheet 19
MMC1_D2: J20.1(DAT2) R81.1 U15.2(IO2) ; also on sheet 19
MMC1_D3: J20.2(CD/DAT3) R80.1 U15.3(IO3) ; also on sheet 19
MMC1_SD_EN: R117.1 U22.1(A) ; also on sheet 39
MMC1_SD_LS_EN: R374.1 U13.3(ON) U22.4(Y)
MMC1_SDCD: J20.9(CD) R96.1 U18.5(IO2) ; also on sheet 19
OSPI0_CSN0: R39.2 U12.F23(OSPI0_CSN0)
OSPI0_LBCLK: R52.1 R53.2
OSPI_CLK: R312.1 R315.1 U12.H24(OSPI0_CLK)
OSPI_CS: R39.1 R304.1 U9.C2(CS#)
OSPI_DQ0: R319.1 RA3.4 U9.D3(DQ0)
OSPI_DQ1: R309.1 RA3.1 U9.D2(DQ1)
OSPI_DQ2: R318.1 RA3.2 U9.C4(DQ2)
OSPI_DQ3: R310.1 RA3.3 U9.D4(DQ3)
OSPI_DQ4: R306.1 RA4.2 U9.D5(DQ4)
OSPI_DQ5: R307.1 RA4.1 U9.E3(DQ5)
OSPI_DQ6: R308.1 RA4.3 U9.E2(DQ6)
OSPI_DQ7: R303.1 RA4.4 U9.E1(DQ7)
OSPI_DQS: R297.1 R305.1 R320.1 U9.C3(DS)
OSPI_DQS_SOC: R53.1 R320.2 U12.J24(OSPI0_DQS)
OSPI_INTn: R317.1 R321.1 U12.H21(OSPI0_CSN2)
OSPI_RSTn: R313.1 U6.4(Y) U9.A4(RESET#)
PORz_OUT: U22.6(C) ; also on sheet 23 24 27 42
RESETSTATz: U6.2(B) U22.3(B) ; also on sheet 13 19 23 24 27 32 33 37 39 40 41 42
SoC_I2C0_SCL: U26.6(SCL) ; also on sheet 10 13 32 33 37 42
SoC_I2C0_SDA: U26.5(SDA) ; also on sheet 10 13 32 33 37 42
SOC_I2C1_SCL: TP71.1(TP) U11.1(SCL) U33.1(SCL) ; also on sheet 14 26 39 40 41 42
SOC_I2C1_SDA: TP72.1(TP) U11.6(SDA) U33.6(SDA) ; also on sheet 14 26 39 40 41 42
SoC_OSPI_DQ0: RA3.5 U12.E25(OSPI0_D0)
SoC_OSPI_DQ1: RA3.8 U12.G24(OSPI0_D1)
SoC_OSPI_DQ2: RA3.7 U12.F25(OSPI0_D2)
SoC_OSPI_DQ3: RA3.6 U12.F24(OSPI0_D3)
SoC_OSPI_DQ4: RA4.7 U12.J23(OSPI0_D4)
SoC_OSPI_DQ5: RA4.8 U12.J25(OSPI0_D5)
SoC_OSPI_DQ6: RA4.6 U12.H25(OSPI0_D6)
SoC_OSPI_DQ7: RA4.5 U12.J22(OSPI0_D7)
TMP1_ADD0: R58.1 U11.5(ADD0)
TMP1_ADD1: R63.1 U11.3(ADD1)
TMP2_ADD1: R140.1 U33.3(ADD1)
N16956470: R52.2 U12.G25(OSPI0_LBCLKO)
N16960510: R321.2 U9.A5(INT#)
N16960546: R312.2 U9.B2(CK)

Not connected (* = marked no-connect by the designer): U9 A2(DNU1)* A3(DNU2)* B1(DNU3)* B5(DNU4)* C5(DNU5)*; U13 4(CT)*; U15 4(NC1)* 9(NC2)*; U18 2(NC)* 3(IO1)*; U33 5(ADD0)*

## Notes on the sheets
sheet 20
- SD CARD INTERFACE
- D-Note :-
  This power switch, along with the power switch supply reset logic, and the host IO power
  supply circuit is required to support UHS-I SD Cards which begins communications
   using 3.3V signal levels and later change to 1.8V signal levels when changing to one of
  the faster data transfer speeds.
  Cycling power to the SD Card is the only way to put it back into 3.3V mode since SD Cards
  do not have a reset pin.
  The host IO power supply must power off/on and change voltage at the same time as the SD
  Card. These circuits and the software driver operating
   the signals sourcing these circuits ensure both devices are off, or on and operating at
  the same IO voltage at the same time.
- SD CARD LOAD SWITCH RESET LOGIC
- LOAD SWITCH
- D-Note :-
  Add a series resistor to the GPIO input
  for isolation or testing
  Refer SK-AM62P-LP schematics
- D-Note :-
  Anding logic could be optimized to 2
  input AND gate
  Use RESETSTATz and the SoC IO as inputs
- D-Note :-
  CT - Add a 220 pF or higher cap for
  SD card supply slew rate control
- D-Note :-
  For UHS-I  operation, the pullups
  are recommended to be connected to
  the 3.3V/1.8V switched LDO output
- Note :-
  MMC1_CLK pullup is a DNI
- D-Note :-
  Ensure internal pullups are not configured when 10K
  external pullups are used. As a good design practice, a
  47K pullup is recommended to ensure the pullup value is
  within the SD card specification, when internal pulls are
  enabled unexpectedly. This way the resulting pull
  resistance will still be within the specified.
- D-Note :-
  Add a filter cap
- CAD Note :-
  Place near SD Card Connector
sheet 21
- OSPI  FLASH
- D-Note :-
  Connecting OSPI interface to multiple devices
  is not recommended or supported
- R-Note
  SOC IO buffers are off during power-up. A pullup
  is recommended near to the attached device, to
  hold the attached device IOs in a known state.
  Use of Pullups are attached device dependent
- D-Note :-
  These 0R resistors are used for configuring QSPI and OSPI
  This is optional during custom board design
- SOC OSPI INTERFACE
- CAD Note :-
  Place OSPI clock series resistor
  near to the SoC clock output
- CAD Note :-
  Place SOC clock
  output pulldown
  resistor near to the
  clock input pin of
  the attached
  (memory) device
- Cad Note :-
  Place series resistor close to the Memory
- D-Note :-
  External loopback clock series resistors
  are DNI when DQS is connected
- R-Note :-
  DQS pulldown is enabled
  Place pulldown closer to the SoC
- CAD Note:- Place R53 close to the
  Memory to avoid stub
- CAD Note:- Place R52 close to the SOC Ball
  with as little trace as possible
- D-NOTE:
  For QSPI Configuration
  Remove 0E resistors from the following
  1.OSPI_DQ4 to OSPI_DQ7 nets (RA4)
  2.OSPI_INTn (R321)
  OSPI NOR Flash can be replaced with the Footprint
  compatible OCTAL NAND Flash (Mfr Part# W35N01JWTBAG)
- D-Note :-
  Choice of QSPI memory device :
  For improved performance, it is
  recommended to select QSPI memory device
  with an external reset input pin
  The reset pin is recommended to be
  controlled using SOC  reset status output
  or an ANDing logic as implemented in the
  starter kit
- OSPI  FLASH RESET
- D-Note :-
  Add a series resistor to the GPIO input
  for isolation or testing
  Refer SK-AM62P-LP schematics
- D-Note :-
  ANDing logic additionally performs level translation
  Verify the Reset IO level compatibility before
  optimizing the reset ANDing logic.
  IO level mismatch could cause supply leakage and
  affect SOC operation
sheet 22
- BOARD ID EEPROM
- I2C ADDRESS: 0X51
- DIGITAL TEMPERATURE SENSORS
- I2C ADDRESS: 0x48
- I2C ADDRESS: 0x49
- CAD NOTE: PLACE TEMP SENSOR CLOSE TO SoC
- CAD NOTE: PLACE TEMP SENSOR CLOSE TO DDR4
- Silk: SOC_I2C1
